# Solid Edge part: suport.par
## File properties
Author: ion
Template: Iso Part.par
Last saved by: user
Revision: 4
Application: Solid Edge
Accuracy: 0.990
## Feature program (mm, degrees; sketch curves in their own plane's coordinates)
sketch for "unnamed Protrusion 1" #1 plane through (0, 0, 0) normal (0, -1, 0) x-axis (1, 0, 0)
  line (10, 10) -> (-10, 10)
  line (-10, 10) -> (-10, -10)
  line (-10, -10) -> (10, -10)
  line (10, -10) -> (10, 10)
sketch for "unnamed Protrusion 1" #2 plane through (0, 0, 0) normal (0, -1, 0) x-axis (1, 0, 0)
  circle centre (0, 0) radius 5
extrude "unnamed Protrusion 1" add finite 25 along -normal
chamfer "Chamfer_1" setback 2
chamfer "Chamfer_2" setback 2
sketch for "Hole_1" plane through (0, 0, 0) normal (0, -1, 0) x-axis (1, 0, 0)
hole "Hole_1" diameter 3 through
pattern "unnamed Pattern 1" of "Hole_1"
pattern "unnamed Pattern 2"
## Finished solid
Body 1: solid body, 15 faces, 34 edges, 16 vertices.
  Faces by surface: plane 10, cylinder 5
  Edges by curve: line 24, circle 10
Bounding box of the edges (mm): 20.000 x 25.000 x 20.000, from (-10, 0, -10) to (10, 25, 10).
Cylindrical faces by radius (mm): R1.5 x4, R5 x1
Planar faces by outward normal: +x 1, +y 1, +z 1, -x 1, -y 1, -z 1, oblique 4
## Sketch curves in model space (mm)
circle centre (0, 0, 0) radius 5
line (10, 0, -10) -> (10, 0, 10)
line (10, 0, 10) -> (-10, 0, 10)
line (-10, 0, 10) -> (-10, 0, -10)
line (-10, 0, -10) -> (10, 0, -10)
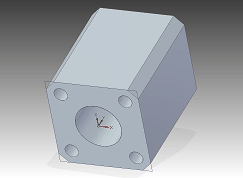
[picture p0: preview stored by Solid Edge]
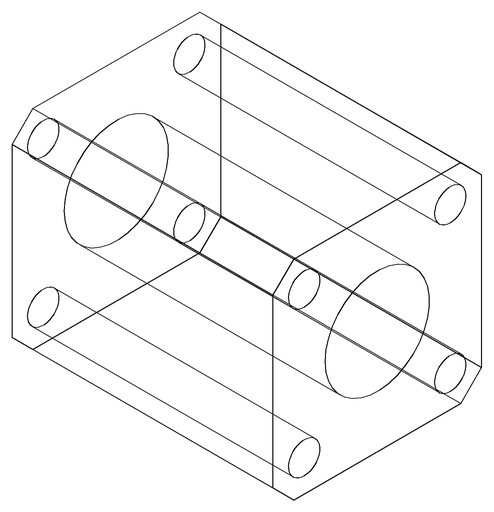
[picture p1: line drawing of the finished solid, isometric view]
